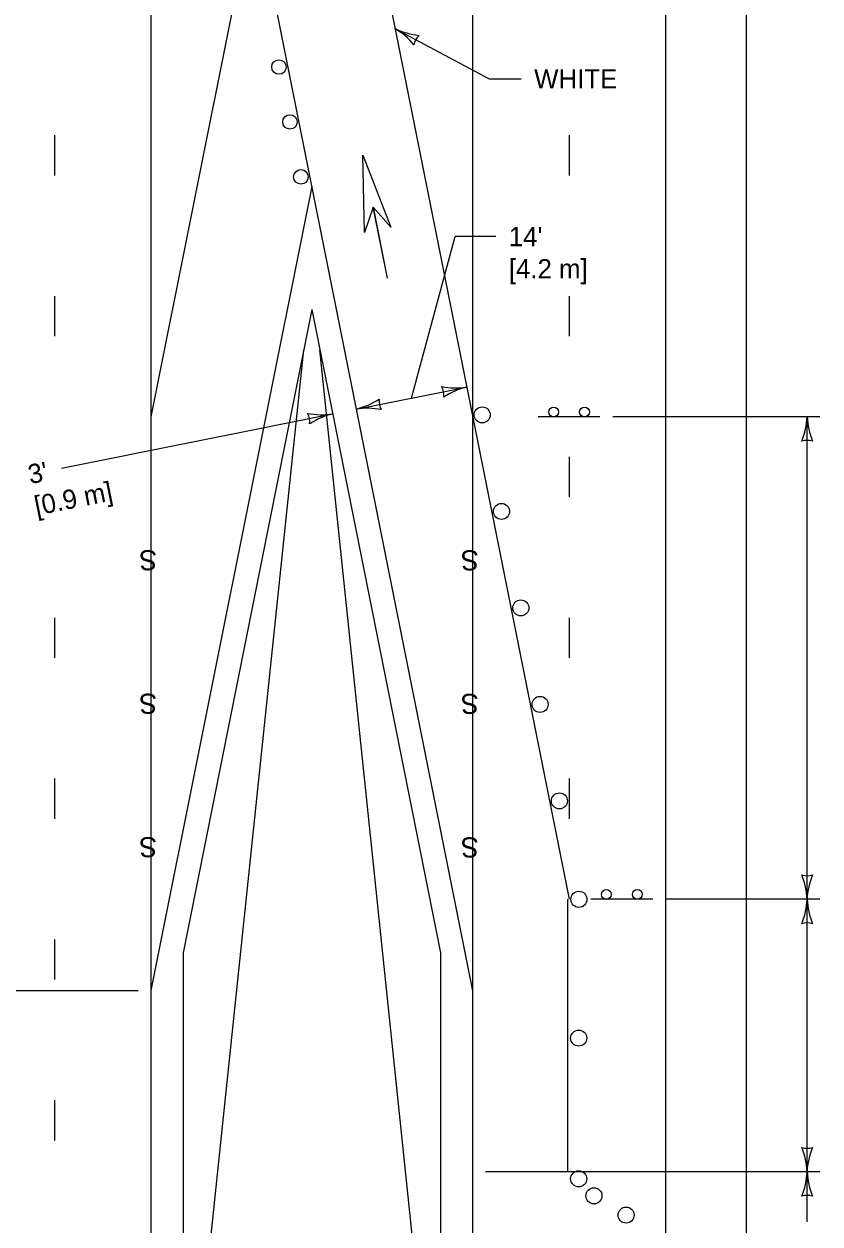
# Model space of a CAD drawing. Extents: x 49991.4 to 50021, y 49987.6 to 50011.4.
# Drawn here: x 50006.491 to 50008.965, y 49989.676 to 49993.407 of the extents above; entities that cross this region are included whole.
import ezdxf

# ---------------------------------------------------------------- set-up
doc = ezdxf.new("R2010")
doc.units = 0
for name, color, linetype in [('Level 1', 7, 'Continuous'), ('Level 2', 7, 'Continuous'), ('Level 3', 7, 'Continuous')]:
    doc.layers.add(name, color=color, linetype=linetype)

msp = doc.modelspace()

# ---------------------------------------------------------------- linework, layer by layer
at = {"layer": 'Level 1'}
for p, q in [((50008.4852, 49998.6725), (50008.4852, 49988.1855)), ((50008.7352, 49998.6725), (50008.7352, 49988.1855)), ((50006.8852, 49997.1855), (50008.1852, 49990.6855)), ((50006.5852, 49996.9011), (50007.8852, 49990.4009)), ((50006.8852, 49995.4011), (50006.8852, 49992.1858)), ((50007.8852, 49995.4012), (50007.8852, 49992.1855)), ((50007.2067, 49993.7934), (50006.8852, 49992.1858)), ((50006.5852, 49993.0607), (50006.5852, 49992.9357)), ((50008.1852, 49993.0607), (50008.1852, 49992.9357)), ((50007.3852, 49992.9012), (50006.8852, 49990.4015)), ((50007.6208, 49992.6161), (50007.5765, 49992.8377)), ((50007.621, 49992.6162), (50007.5767, 49992.8377)), ((50006.5852, 49992.5607), (50006.5852, 49992.4357)), ((50008.1852, 49992.5607), (50008.1852, 49992.4357)), ((50007.3852, 49992.519), (50006.9852, 49990.5193)), ((50007.3852, 49992.519), (50007.7852, 49990.5187)), ((50006.9852, 49988.8042), (50007.3601, 49992.3936)), ((50007.7852, 49988.8042), (50007.4103, 49992.3936)), ((50006.8852, 49992.1858), (50006.8852, 49990.4015)), ((50007.8852, 49992.1855), (50007.8852, 49990.4009)), ((50008.1852, 49992.1855), (50008.0892, 49992.1855)), ((50008.2812, 49992.1855), (50008.1852, 49992.1855)), ((50008.1852, 49992.0607), (50008.1852, 49991.9357)), ((50006.5852, 49991.5607), (50006.5852, 49991.4357)), ((50008.1852, 49991.5607), (50008.1852, 49991.4357)), ((50006.5852, 49991.0607), (50006.5852, 49990.9357)), ((50008.1852, 49991.0607), (50008.1852, 49990.9357)), ((50008.1804, 49990.6855), (50008.1804, 49989.8382)), ((50008.3492, 49990.6855), (50008.2532, 49990.6855)), ((50008.4452, 49990.6855), (50008.3492, 49990.6855)), ((50006.5852, 49990.5607), (50006.5852, 49990.4357)), ((50006.9852, 49990.5193), (50006.9852, 49988.1255)), ((50007.7852, 49990.5187), (50007.7852, 49988.1855)), ((50006.8852, 49990.4015), (50006.8852, 49988.1255)), ((50007.8852, 49990.4009), (50007.8852, 49989.8382)), ((50006.5852, 49990.0607), (50006.5852, 49989.9357)), ((50007.8852, 49989.8382), (50007.8852, 49988.1855))]:
    msp.add_line(p, q, dxfattribs=at)
msp.add_lwpolyline([(50007.5495, 49992.7586), (50007.5442, 49992.9987), (50007.6315, 49992.7749), (50007.5765, 49992.8375)], close=True, dxfattribs=at)
for centre, radius in [((50007.2834, 49993.2727), 0.0225), ((50007.3175, 49993.102), 0.0225), ((50007.3515, 49992.9313), 0.0225), ((50007.9151, 49992.1914), 0.025), ((50008.1372, 49992.2005), 0.0152), ((50008.2331, 49992.2006), 0.0152), ((50007.9751, 49991.8914), 0.025), ((50008.0351, 49991.5914), 0.025), ((50008.0951, 49991.2914), 0.025), ((50008.1551, 49990.9914), 0.025), ((50008.2157, 49990.6854), 0.025), ((50008.3012, 49990.7005), 0.0152), ((50008.3971, 49990.7006), 0.0152), ((50008.2151, 49990.2539), 0.025), ((50008.2151, 49989.8164), 0.025), ((50008.2625, 49989.7637), 0.025), ((50008.2625, 49989.7637), 0.025), ((50008.2625, 49989.7637), 0.025), ((50008.3625, 49989.7038), 0.025)]:
    msp.add_circle(centre, radius, dxfattribs=at)
at = {"layer": 'Level 3'}
for p, q in [((50007.6438, 49993.3924), (50007.9365, 49993.2362)), ((50007.9365, 49993.2362), (50008.0365, 49993.2362)), ((50007.6951, 49992.2436), (50007.831, 49992.7457)), ((50007.9578, 49992.7457), (50007.831, 49992.7457)), ((50007.5235, 49992.2093), (50007.8667, 49992.278)), ((50006.6071, 49992.026), (50007.4501, 49992.1946)), ((50008.9652, 49992.1855), (50008.3212, 49992.1855)), ((50008.9252, 49990.6855), (50008.9252, 49992.1855)), ((50008.9652, 49990.6855), (50008.4852, 49990.6855)), ((50008.9252, 49989.6823), (50008.9252, 49990.6855)), ((50005.4652, 49990.4015), (50006.8452, 49990.4015)), ((50008.9652, 49989.8382), (50007.9252, 49989.8382))]:
    msp.add_line(p, q, dxfattribs=at)
for centre, radius, start, end in [((50007.5312, 49993.2007), 0.2223, 39.3678, 59.5513), ((50007.7433, 49993.6031), 0.233, 244.7391, 263.989), ((50007.7569, 49993.332), 0.0548, 134.0506, 169.773), ((50007.8321, 49992.4976), 0.2223, 258.7641, 278.9477), ((50007.741, 49992.2528), 0.0548, 353.447, 29.1693), ((50007.9236, 49992.052), 0.233, 104.1354, 123.3853), ((50007.4666, 49992.4353), 0.233, 284.1354, 303.3853), ((50007.6493, 49992.2345), 0.0548, 173.447, 209.1693), ((50007.4155, 49992.4142), 0.2223, 258.7641, 278.9477), ((50007.3243, 49992.1695), 0.0548, 353.447, 29.1693), ((50007.507, 49991.9687), 0.233, 104.1354, 123.3853), ((50007.5581, 49991.9897), 0.2223, 78.7641, 98.9477), ((50008.7031, 49992.1947), 0.2223, 337.456, 357.6395), ((50009.1579, 49992.197), 0.233, 182.8273, 202.0772), ((50008.9252, 49992.0573), 0.0548, 72.1388, 107.8612), ((50008.9252, 49990.8137), 0.0548, 252.1388, 287.8612), ((50008.6925, 49990.674), 0.233, 2.8273, 22.0772), ((50009.1473, 49990.6763), 0.2223, 157.456, 177.6395), ((50008.7031, 49990.6947), 0.2223, 337.456, 357.6395), ((50009.1579, 49990.697), 0.233, 182.8273, 202.0772), ((50008.9252, 49990.5573), 0.0548, 72.1388, 107.8612), ((50008.9252, 49989.9664), 0.0548, 252.1388, 287.8612), ((50008.6925, 49989.8267), 0.233, 2.8273, 22.0772), ((50009.1473, 49989.829), 0.2223, 157.456, 177.6395), ((50008.7031, 49989.8474), 0.2223, 337.456, 357.6395), ((50009.1579, 49989.8497), 0.233, 182.8273, 202.0772), ((50008.9252, 49989.71), 0.0548, 72.1388, 107.8612)]:
    msp.add_arc(centre, radius, start, end, dxfattribs=at)

# ---------------------------------------------------------------- texts
at = {"layer": 'Level 1'}
for p in [(50006.9044, 49991.7709), (50007.9044, 49991.7706), (50006.9044, 49991.3248), (50007.9044, 49991.3244), (50006.9044, 49990.8788), (50007.9044, 49990.8782)]:
    msp.add_text('S', height=0.0625, rotation=180, dxfattribs=at).set_placement(p)
at = {"layer": 'Level 2'}
for s, p in [('WHITE', (50008.0765, 49993.2062)), ("14'", (50007.9978, 49992.7157)), ('[4.2 m]', (50007.9978, 49992.6157))]:
    msp.add_text(s, height=0.06, dxfattribs=at).set_placement(p)
for s, p in [("3'", (50006.51, 49991.976)), ('[0.9 m]', (50006.5296, 49991.8781))]:
    msp.add_text(s, height=0.06, rotation=11.3105, dxfattribs=at).set_placement(p)

doc.saveas('drawing.dxf')
